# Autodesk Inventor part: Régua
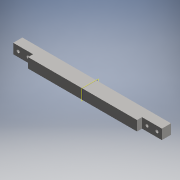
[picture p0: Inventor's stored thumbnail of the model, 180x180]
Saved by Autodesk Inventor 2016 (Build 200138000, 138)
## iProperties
Created: 2016-02
Part Number: Régua
Material: Steel, Carbon
Document SubType Name: Modeling
Designer: Vertex
Density: 7.85 g/cm^3
Appearance: Semi-Polished
Mass: 1248.24 g
Surface Area: 308.183 cm^2
Volume: 159.012 cm^3
Author: Vertex
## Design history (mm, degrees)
sketch "Sketch1"
  geometry: L1 (0, 0)-(300, 0); L2 (300, 0)-(300, 20); L3 (300, 20)-(0, 20); L4 (0, 20)-(0, 0); L5 (0, 20)-(0, 0); L6 (40, 20)-(40, 0); L7 (300, 20)-(300, 0); L8 (260, 0)-(260, 20)
  constraints: 16 end point, 5 equal length, 1 horizontal, 1 perpendicular, 1 vertical
  dimensions: "d0" = 300 distance of L3.end L2.end; "d1" = 20 distance of L2.end L1.end; "d2" = 40 distance between parallel lines of L4 L6; "d3" = 40 distance between parallel lines of L2 L8
extrude "Extrusion1" new body sketch "Sketch1" distance "d4" = 20; taper "d5" = 0 deg
sketch "Sketch2"
  geometry: L1 (0, 0)-(300, 0); L2 (300, 0)-(300, 20); L3 (300, 20)-(0, 20); L4 (300, 20)-(0, 20) reference; L5 (0, 20)-(0, 0); L6 (0, 0)-(300, 0) reference; L7 (300, 20)-(300, 0); L8 (260, 0)-(260, 20); L9 (40, 20)-(40, 0)
  constraints: 8 end point, 4 point on line, 2 parallel, 1 perpendicular, 1 vertical
  dimensions: "d6" = 40 distance between parallel lines of L2 L8; "d7" = 40 distance between parallel lines of L5 L9
extrude "Extrusion2" join sketch "Sketch2" distance "d8" = 10; taper "d9" = 0 deg
workplane "Work Plane1"
chamfer "Chamfer1" distance "d28" = 1.5; stored, may be unused: second distance "d29" = 1.25, angle "d30" = 45 deg
hole "Hole3" diameter "d33" = 6; stored, may be unused: countersink angle "d37" = 90 deg, drill point angle "d39" = 118 deg; dims "d31" = 10, "d32" = 10, "d34" = 7.5, "d35" = 10, "d36" = 10, "d38" = 10
hole "Hole4" diameter "d42" = 6; stored, may be unused: countersink angle "d46" = 90 deg, drill point angle "d48" = 118 deg; dims "d40" = 30, "d41" = 10, "d43" = 7.5, "d44" = 10, "d45" = 10, "d47" = 10
mirror "Mirror2"
body "Solid1"
